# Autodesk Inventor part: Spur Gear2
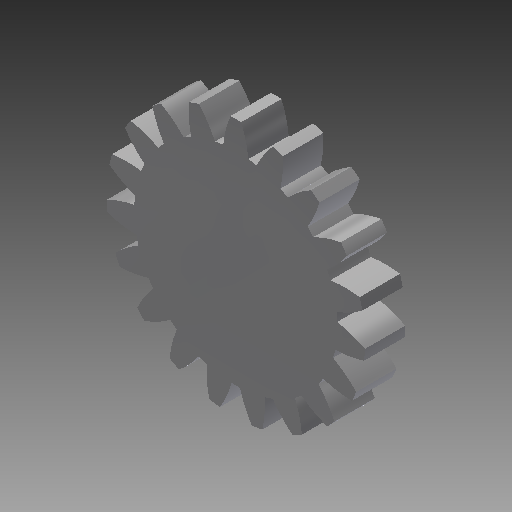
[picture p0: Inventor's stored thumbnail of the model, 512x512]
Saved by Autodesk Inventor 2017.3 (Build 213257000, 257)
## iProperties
Created: 2020-03
Part Number: Spur Gear2
Material: Steel
Document SubType Name: Modeling
Designer: Tim_G
Categories: <?xml version="1.0" encoding="UTF-16"?> <MemberInstance><Categories><FamilyTemplate><FamilyTemplateParameter ValueType="xs:double" Id="1" ObjectReferenceKey="da
Density: 1 g/cm^3
Appearance: Steel
CustomPartVersion: 1
Author: Tim_G
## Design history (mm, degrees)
sketch "Sketch1"
  geometry: C1 r 15.991 at (0, 0)
  constraints: 1 centre point
  dimensions: "d0" = 31.98165 diameter of C1 (= da_da)
extrude "Extrusion1" new body sketch "Sketch1" distance "d1" = 5 (= da_b); taper "d2" = 0 deg
workplane "Work Plane2"
sketch "Sketch2"
  geometry: C1 r 15.991 at (0, 0) reference; C2 r 14.468 at (0, 0)
  constraints: 1 centre point, 1 coincident
  dimensions: "d3" = 28.93578 diameter of C2 (= da_dw)
feature "Pitch Diameter" sketch "Sketch2" dims "d4" = 10, "d5" = 0
workplane "Work Plane8"
workplane "Work Plane9"
feature "Spur Gear" dims "da_b" = 5, "da_d" = 28.93578, "da_aw" = 25.12844, "da_da" = 31.98165, "da_df" = 25.12844, "da_dw" = 28.93578, angle "da_beta" = 0 deg, "da_lefttooth" = 0, "da_righttooth" = 0
body "Solid1"
body "Srf1"
other parameters: "d16" = 25.12844 (= da_aw), "d17" = 0, "d34" = 1.65347 (computed from da_z), "d39" = 0, "d41" = 0, "d43" = 25.12844 (= da_aw), "d46" = 25.12844 (= da_aw), "d47" = 0, "d48" = 0
